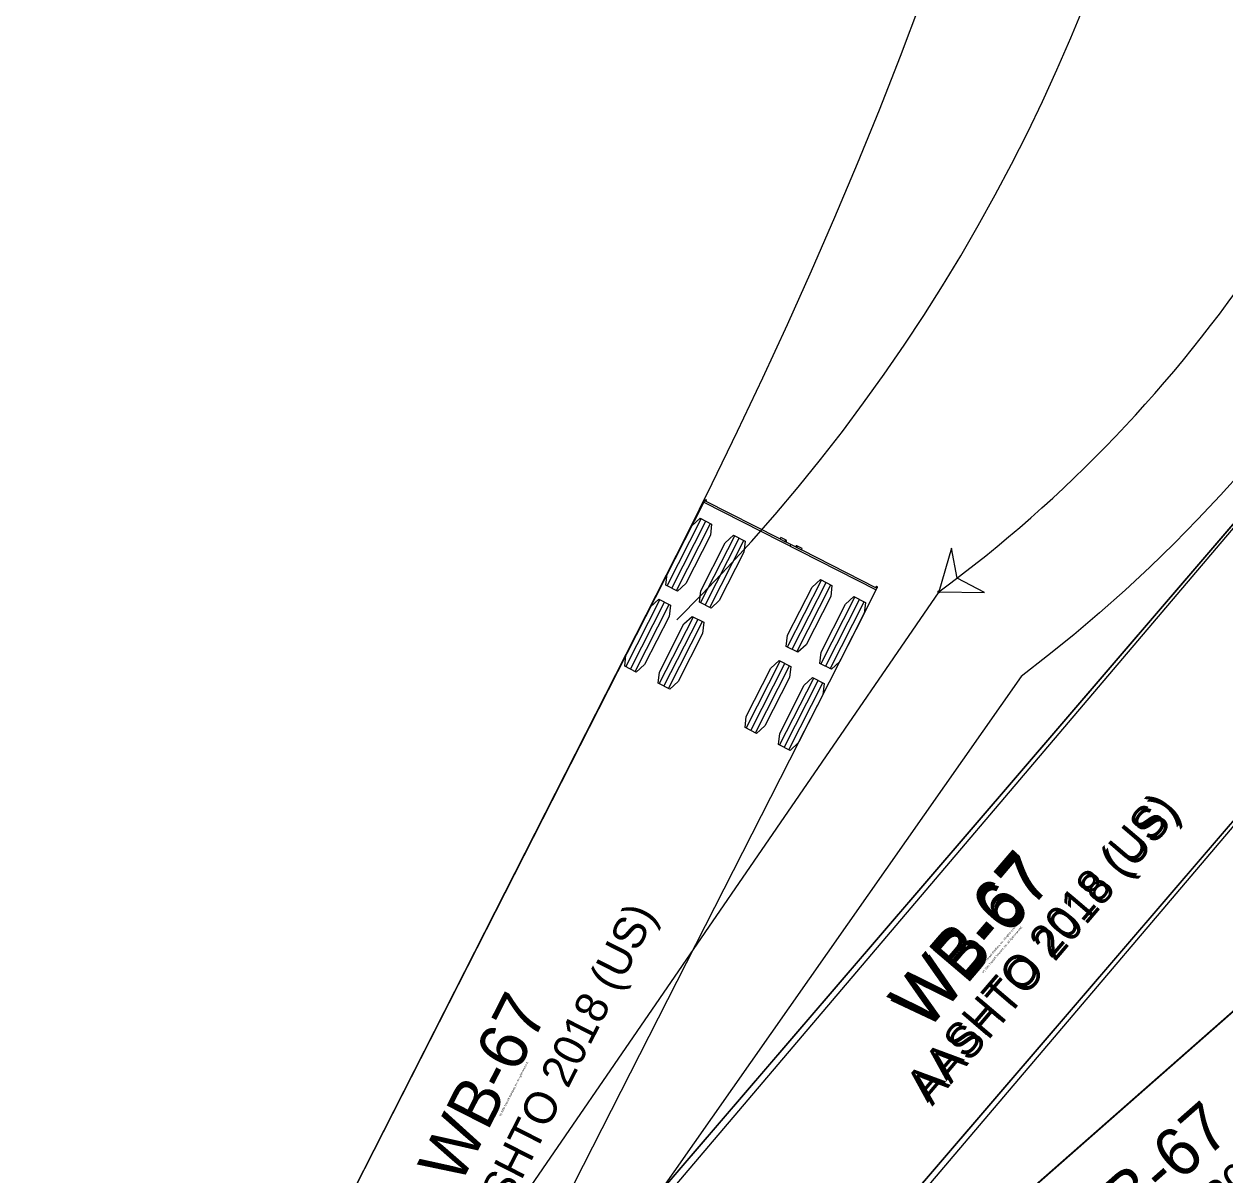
# Model space of a CAD drawing. Extents: x 973688 to 979179, y 703586 to 707602.
# Drawn here: x 976470.8 to 976523.6, y 705436.7 to 705487.3 of the extents above; entities that cross this region are included whole.
import ezdxf

# ---------------------------------------------------------------- set-up
doc = ezdxf.new("R2010")
doc.units = 0
for name, color, linetype in [('EB Right', 7, 'Continuous'), ('NB Left', 7, 'Continuous'), ('NB Right', 7, 'Continuous'), ('R_Prop EP', 7, 'Continuous')]:
    doc.layers.add(name, color=color, linetype=linetype)

msp = doc.modelspace()

# ---------------------------------------------------------------- linework, layer by layer
at = {"layer": 'EB Right'}
for p, q in [((976500.699, 705466.263), (976508.274, 705462.407)), ((976499.085, 705462.587), (976500.582, 705465.528)), ((976499.289, 705462.483), (976500.786, 705465.424)), ((976499.493, 705462.379), (976500.991, 705465.32)), ((976500.555, 705461.838), (976502.053, 705464.779)), ((976500.76, 705461.734), (976502.257, 705464.675)), ((976500.964, 705461.63), (976502.461, 705464.571)), ((976504.045, 705464.639), (976504.282, 705464.519)), ((976504.519, 705464.398), (976504.487, 705464.335)), ((976504.756, 705464.278), (976504.992, 705464.157)), ((976504.372, 705459.895), (976505.87, 705462.836)), ((976511.032, 705462.319), (976470.818, 705403.835)), ((976504.577, 705459.791), (976506.074, 705462.732)), ((976504.781, 705459.687), (976506.278, 705462.628)), ((976497.27, 705459.022), (976498.767, 705461.963)), ((976497.474, 705458.918), (976498.972, 705461.859)), ((976497.679, 705458.814), (976499.176, 705461.755)), ((976505.843, 705459.146), (976507.34, 705462.087)), ((976506.047, 705459.042), (976507.544, 705461.983)), ((976506.251, 705458.938), (976507.748, 705461.879)), ((976498.741, 705458.274), (976500.238, 705461.215)), ((976498.945, 705458.17), (976500.442, 705461.111)), ((976499.149, 705458.066), (976500.646, 705461.007)), ((976502.558, 705456.33), (976504.055, 705459.271)), ((976502.762, 705456.226), (976504.259, 705459.167)), ((976502.966, 705456.122), (976504.463, 705459.063)), ((976504.028, 705455.582), (976505.525, 705458.523)), ((976504.232, 705455.478), (976505.729, 705458.419)), ((976504.437, 705455.374), (976505.934, 705458.315))]:
    msp.add_line(p, q, dxfattribs=at)
for points in [[(976477.342, 705420.384), (976499.937, 705464.787), (976501.066, 705467.07), (976502.181, 705469.374), (976503.289, 705471.716), (976504.372, 705474.063), (976505.427, 705476.414), (976506.454, 705478.769), (976507.451, 705481.127), (976508.415, 705483.488), (976509.346, 705485.851), (976510.24, 705488.215)], [(976524.389, 705467.652), (976523.408, 705466.56), (976522.4, 705465.487), (976521.365, 705464.433), (976520.301, 705463.398), (976519.209, 705462.384), (976518.088, 705461.39), (976516.958, 705460.432), (976515.809, 705459.504), (976514.638, 705458.597), (976490.06, 705423.558)], [(976500.751, 705466.316), (976500.732, 705466.326), (976500.7, 705466.263), (976498.128, 705461.213), (976476.718, 705419.158), (976480.505, 705417.23), (976484.292, 705415.302), (976505.703, 705457.357), (976508.274, 705462.407), (976508.306, 705462.47), (976508.286, 705462.48)], [(976504.317, 705464.58), (976504.079, 705464.701), (976504.077, 705464.702), (976504.046, 705464.639), (976504.014, 705464.655), (976500.774, 705466.305), (976500.773, 705466.305)], [(976504.75, 705464.281), (976504.285, 705464.517)], [(976508.265, 705462.491), (976508.264, 705462.491), (976505.024, 705464.141), (976504.992, 705464.157), (976505.024, 705464.22), (976505.023, 705464.221), (976504.785, 705464.342)], [(976511.032, 705462.319), (976513.032, 705462.28), (976511.837, 705462.912), (976511.587, 705464.241), (976511.032, 705462.319)]]:
    msp.add_lwpolyline(points, dxfattribs=at)
for points in [[(976499.544, 705462.353), (976499.034, 705462.613), (976499.09, 705463.103), (976500.168, 705465.22), (976500.531, 705465.554), (976501.041, 705465.294), (976500.985, 705464.804), (976499.907, 705462.687)], [(976501.014, 705461.605), (976500.505, 705461.864), (976500.561, 705462.354), (976501.639, 705464.471), (976502.002, 705464.805), (976502.512, 705464.545), (976502.456, 705464.056), (976501.378, 705461.938)], [(976511.032, 705462.319), (976513.032, 705462.28), (976511.837, 705462.912), (976511.587, 705464.241)], [(976504.832, 705459.661), (976504.322, 705459.921), (976504.378, 705460.411), (976505.456, 705462.528), (976505.819, 705462.862), (976506.329, 705462.602), (976506.273, 705462.112), (976505.195, 705459.995)], [(976497.729, 705458.789), (976497.219, 705459.048), (976497.276, 705459.538), (976498.353, 705461.655), (976498.717, 705461.989), (976499.226, 705461.729), (976499.17, 705461.24), (976498.092, 705459.122)], [(976506.302, 705458.913), (976505.792, 705459.172), (976505.848, 705459.662), (976506.926, 705461.78), (976507.289, 705462.113), (976507.799, 705461.854), (976507.743, 705461.364), (976506.665, 705459.246)], [(976499.2, 705458.04), (976498.69, 705458.3), (976498.746, 705458.789), (976499.824, 705460.907), (976500.187, 705461.24), (976500.697, 705460.981), (976500.641, 705460.491), (976499.563, 705458.374)], [(976503.017, 705456.097), (976502.507, 705456.356), (976502.563, 705456.846), (976503.641, 705458.963), (976504.004, 705459.297), (976504.514, 705459.037), (976504.458, 705458.548), (976503.38, 705456.43)], [(976504.487, 705455.348), (976503.977, 705455.608), (976504.033, 705456.097), (976505.111, 705458.215), (976505.475, 705458.548), (976505.984, 705458.289), (976505.928, 705457.799), (976504.85, 705455.682)]]:
    msp.add_lwpolyline(points, close=True, dxfattribs=at)
for centre, radius in [((976500.778, 705466.341), 0.0266), ((976508.291, 705462.516), 0.0266), ((976511.032, 705462.319), 0.0417), ((976511.032, 705462.319), 0.0417)]:
    msp.add_circle(centre, radius, dxfattribs=at)
for centre, radius, start, end in [((976475.499, 705510.544), 59.902, 306.38359, 345.81077), ((976501.669, 705468.118), 2.022, 243.0189, 243.7027), ((976504.3, 705464.549), 0.0354, 67.3105, 239.4959), ((976504.301, 705464.549), 0.0352, 243.9933, 62.9937), ((976504.769, 705464.31), 0.0352, 63.0442, 242.0446), ((976504.77, 705464.31), 0.0353, 246.3551, 64.7048), ((976508.291, 705462.516), 0.0363, 262.0964, 223.2577)]:
    msp.add_arc(centre, radius, start, end, dxfattribs=at)
at = {"layer": 'NB Left'}
for points in [[(976597.405, 705538.82), (976596.514, 705537.482), (976595.572, 705536.185), (976594.585, 705534.932), (976587.989, 705527.228), (976586.467, 705525.264), (976584.967, 705523.4), (976583.486, 705521.619), (976499.872, 705424.179), (976493.422, 705429.715), (976493.503, 705429.81), (976493.503, 705429.81)], [(976493.503, 705429.81), (976548.212, 705493.558), (976551.549, 705497.487), (976554.723, 705501.298), (976556.225, 705503.144), (976557.662, 705504.95), (976559.033, 705506.718), (976560.337, 705508.453)], [(976499.901, 705424.248), (976499.917, 705424.234), (976499.963, 705424.287), (976503.655, 705428.587), (976534.391, 705464.397), (976531.166, 705467.165), (976527.941, 705469.933), (976497.205, 705434.123), (976493.515, 705429.822), (976493.469, 705429.769), (976493.485, 705429.754)], [(976500.184, 705424.036), (976500.2, 705424.022), (976500.246, 705424.076), (976503.916, 705428.395), (976534.47, 705464.36), (976531.231, 705467.111), (976527.992, 705469.863), (976497.438, 705433.898), (976493.769, 705429.578), (976493.723, 705429.525), (976493.74, 705429.511)]]:
    msp.add_lwpolyline(points, dxfattribs=at)
at = {"layer": 'NB Right'}
for points in [[(976498.963, 705421.903), (976539.356, 705457.419), (976541.354, 705459.14), (976543.373, 705460.839), (976546.949, 705463.767), (976554.249, 705470.181), (976556.417, 705471.735), (976558.606, 705473.268), (976560.818, 705474.782)], [(976504.508, 705415.49), (976504.522, 705415.474), (976504.575, 705415.52), (976508.832, 705419.262), (976544.271, 705450.425), (976541.464, 705453.617), (976538.658, 705456.808), (976503.219, 705425.645), (976498.963, 705421.902), (976498.91, 705421.855), (976498.925, 705421.839)]]:
    msp.add_lwpolyline(points, dxfattribs=at)
at = {"layer": 'R_Prop EP'}
msp.add_arc((976443.17, 705517.879), 80, 314.77291, 25.44389, dxfattribs=at)

# ---------------------------------------------------------------- texts
at = {"layer": 'EB Right'}
for s, height, p in [('AASHTO 2018 (US)', 1.41667, (976490.95, 705433.047)), ('WB-67', 2.125, (976489.966, 705436.188)), ('(c) 2020 Transoft Solutions, Inc. All rights reserved.', 0.085, (976491.776, 705439.275))]:
    msp.add_text(s, height=height, rotation=63.0189, dxfattribs=at).set_placement(p)
at = {"layer": 'NB Left'}
for s, height, rotation, p in [('AASHTO 2018 (US)', 1.41667, 49.3605, (976510.532, 705439.851)), ('AASHTO 2018 (US)', 1.41667, 49.6504, (976510.735, 705439.693)), ('WB-67', 2.125, 49.3605, (976510.317, 705443.136)), ('WB-67', 2.125, 49.6504, (976510.504, 705442.977)), ('(c) 2020 Transoft Solutions, Inc. All rights reserved.', 0.085, 49.3605, (976512.805, 705445.708)), ('(c) 2020 Transoft Solutions, Inc. All rights reserved.', 0.085, 49.6504, (976512.979, 705445.562))]:
    msp.add_text(s, height=height, rotation=rotation, dxfattribs=at).set_placement(p)
at = {"layer": 'NB Right'}
for s, height, p in [('AASHTO 2018 (US)', 1.41667, (976517.215, 705429.454)), ('WB-67', 2.125, (976517.462, 705432.737))]:
    msp.add_text(s, height=height, rotation=41.3269, dxfattribs=at).set_placement(p)

doc.saveas('drawing.dxf')
